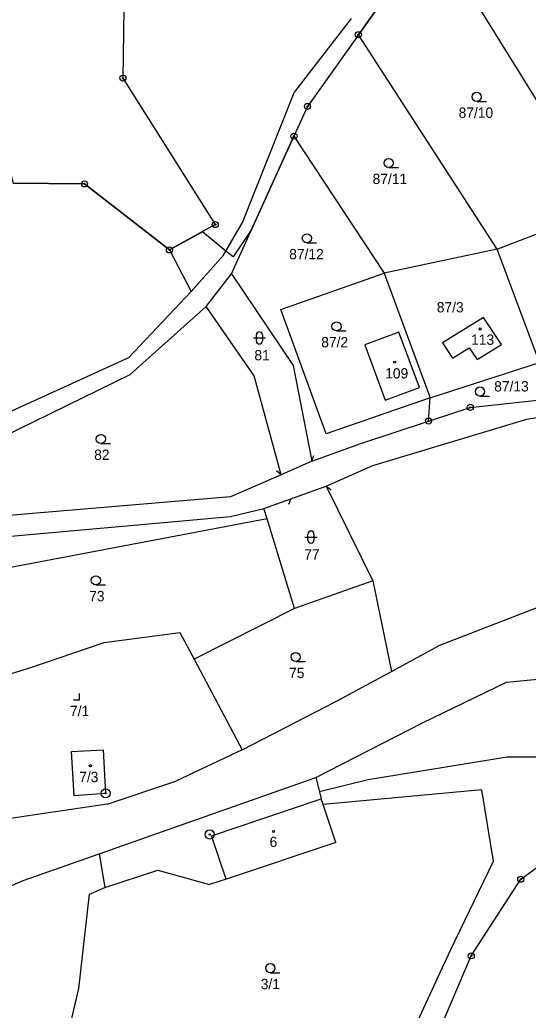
# Model space of a CAD drawing. Extents: x -547623 to -538651, y -1096714 to -1086522.
# Drawn here: x -544678.6 to -544594.9, y -1094562.5 to -1094399.5 of the extents above; entities that cross this region are included whole.
import ezdxf

# ---------------------------------------------------------------- set-up
doc = ezdxf.new("R2010")
doc.units = 0
for name, color, linetype in [('Vrstva 1', 7, 'Continuous'), ('Vrstva 25', 7, 'Continuous'), ('Vrstva 33', 7, 'Continuous'), ('Vrstva 40', 7, 'Continuous'), ('Vrstva 41', 7, 'Continuous'), ('Vrstva 52', 7, 'Continuous'), ('Vrstva 83', 7, 'Continuous'), ('Vrstva 86', 7, 'Continuous'), ('Vrstva 90', 7, 'Continuous'), ('Vrstva 92', 7, 'Continuous')]:
    doc.layers.add(name, color=color, linetype=linetype)

msp = doc.modelspace()

# ---------------------------------------------------------------- linework, layer by layer
at = {"layer": 'Vrstva 1'}
for points in [[(-544622.89, -1094401.93), (-544610.79, -1094384.91)], [(-544610.79, -1094384.91), (-544582.52, -1094430.48)], [(-544624.08, -1094399.23), (-544633.42, -1094411.33)], [(-544622.89, -1094401.93), (-544631.27, -1094413.72)], [(-544600.01, -1094437.2), (-544622.89, -1094401.93)], [(-544641.95, -1094432.83), (-544633.42, -1094411.33)], [(-544631.27, -1094413.72), (-544633.49, -1094418.62)], [(-544643.78, -1094441.26), (-544633.49, -1094418.62)], [(-544633.49, -1094418.62), (-544618.63, -1094441.16)], [(-544600.01, -1094437.2), (-544582.52, -1094430.48)], [(-544645.1, -1094438.2), (-544641.95, -1094432.83)], [(-544654, -1094437.34), (-544650.42, -1094444.2)], [(-544600.01, -1094437.2), (-544618.63, -1094441.16)], [(-544593.06, -1094455.85), (-544600.01, -1094437.2)], [(-544650.42, -1094444.2), (-544645.1, -1094438.2)], [(-544635.64, -1094447.17), (-544618.63, -1094441.16)], [(-544618.63, -1094441.16), (-544611.09, -1094461.67)], [(-544647.95, -1094446.63), (-544643.78, -1094441.26)], [(-544643.78, -1094441.26), (-544633.6, -1094456.35)], [(-544660.7, -1094455.03), (-544650.42, -1094444.2)], [(-544660.47, -1094457.87), (-544647.95, -1094446.63)], [(-544640.06, -1094458.09), (-544647.95, -1094446.63)], [(-544628.17, -1094467.63), (-544635.64, -1094447.17)], [(-544602.27, -1094448.47), (-544609.06, -1094452.61)], [(-544599.29, -1094452.91), (-544602.27, -1094448.47)], [(-544616.21, -1094450.89), (-544621.82, -1094452.97)], [(-544612.84, -1094460), (-544616.21, -1094450.89)], [(-544609.06, -1094452.61), (-544607.38, -1094455.15)], [(-544621.82, -1094452.97), (-544618.48, -1094462.05)], [(-544607.38, -1094455.15), (-544604.64, -1094453.45)], [(-544604.64, -1094453.45), (-544603.3, -1094455.4)], [(-544603.3, -1094455.4), (-544599.29, -1094452.91)], [(-544686.29, -1094466.69), (-544660.7, -1094455.03)], [(-544611.09, -1094461.67), (-544593.06, -1094455.85)], [(-544633.6, -1094456.35), (-544630.56, -1094472.1)], [(-544705.17, -1094479.66), (-544660.47, -1094457.87)], [(-544635.61, -1094474.35), (-544640.06, -1094458.09)], [(-544618.48, -1094462.05), (-544612.84, -1094460)], [(-544611.09, -1094461.67), (-544628.17, -1094467.63)], [(-544611.34, -1094465.51), (-544611.09, -1094461.67)], [(-544604.47, -1094463.25), (-544590.39, -1094461.72)], [(-544611.34, -1094465.51), (-544604.47, -1094463.25)], [(-544595.15, -1094465.22), (-544586.29, -1094463.78)], [(-544622.5, -1094469.18), (-544611.34, -1094465.51)], [(-544620.52, -1094472.8), (-544595.15, -1094465.22)], [(-544630.56, -1094472.1), (-544622.5, -1094469.18)], [(-544630.56, -1094472.1), (-544635.61, -1094474.35)], [(-544628.2, -1094476.24), (-544620.52, -1094472.8)], [(-544635.61, -1094474.35), (-544643.93, -1094478)], [(-544634.01, -1094478.3), (-544628.2, -1094476.24)], [(-544628.2, -1094476.24), (-544620.49, -1094491.8)], [(-544643.93, -1094478), (-544695.48, -1094482.29)], [(-544638.46, -1094479.88), (-544634.01, -1094478.3)], [(-544643.93, -1094481.2), (-544638.46, -1094479.88)], [(-544637.93, -1094481.62), (-544638.46, -1094479.88)], [(-544693.6, -1094485.63), (-544643.93, -1094481.2)], [(-544637.93, -1094481.62), (-544692.61, -1094491.98)], [(-544633.39, -1094496.36), (-544637.93, -1094481.62)], [(-544620.49, -1094491.8), (-544633.39, -1094496.36)], [(-544620.49, -1094491.8), (-544617.45, -1094506.72)], [(-544609.47, -1094502.39), (-544588.64, -1094494.3)], [(-544633.39, -1094496.36), (-544649.95, -1094504.68)], [(-544664.76, -1094501.96), (-544652.27, -1094500.32)], [(-544652.27, -1094500.32), (-544649.95, -1094504.68)], [(-544677.13, -1094506.19), (-544664.76, -1094501.96)], [(-544617.45, -1094506.72), (-544609.47, -1094502.39)], [(-544649.95, -1094504.68), (-544642.01, -1094519.59)], [(-544682.04, -1094507.65), (-544677.13, -1094506.19)], [(-544626.49, -1094511.62), (-544617.45, -1094506.72)], [(-544598.49, -1094508.48), (-544578.51, -1094506.58)], [(-544612.35, -1094515.15), (-544598.49, -1094508.48)], [(-544642.01, -1094519.59), (-544626.49, -1094511.62)], [(-544629.87, -1094524.18), (-544612.35, -1094515.15)], [(-544670.13, -1094519.91), (-544664.93, -1094519.61)], [(-544669.71, -1094527.18), (-544670.13, -1094519.91)], [(-544664.93, -1094519.61), (-544664.52, -1094526.81)], [(-544642.01, -1094519.59), (-544652.94, -1094524.78)], [(-544598.37, -1094520.83), (-544621.29, -1094524.57)], [(-544580.7, -1094520.84), (-544598.37, -1094520.83)], [(-544665.59, -1094536.73), (-544629.87, -1094524.18)], [(-544629.87, -1094524.18), (-544629.3, -1094526.55)], [(-544664.25, -1094528.58), (-544652.94, -1094524.78)], [(-544621.29, -1094524.57), (-544629.3, -1094526.55)], [(-544664.52, -1094526.81), (-544669.71, -1094527.18)], [(-544629.3, -1094526.55), (-544629.02, -1094527.69)], [(-544602.55, -1094526.18), (-544628.7, -1094528.63)], [(-544600.65, -1094537.96), (-544602.55, -1094526.18)], [(-544664.25, -1094528.58), (-544682.08, -1094531.21)], [(-544628.7, -1094528.63), (-544629.02, -1094527.69)], [(-544626.62, -1094534.84), (-544628.7, -1094528.63)], [(-544596.14, -1094540.91), (-544586.8, -1094534.1)], [(-544626.62, -1094534.84), (-544644.68, -1094540.9)], [(-544678.07, -1094541.11), (-544665.59, -1094536.73)], [(-544665.59, -1094536.73), (-544664.64, -1094542.29)], [(-544607.73, -1094552.57), (-544600.65, -1094537.96)], [(-544664.64, -1094542.29), (-544655.9, -1094539.42)], [(-544655.9, -1094539.42), (-544647.38, -1094541.8)], [(-544715.7, -1094557.57), (-544678.07, -1094541.11)], [(-544644.68, -1094540.9), (-544647.38, -1094541.8)], [(-544604.3, -1094553.52), (-544596.14, -1094540.91)], [(-544668.91, -1094558.89), (-544667.17, -1094543.38)], [(-544667.17, -1094543.38), (-544664.64, -1094542.29)], [(-544623.57, -1094598.79), (-544604.3, -1094553.52)], [(-544622.59, -1094584.75), (-544607.73, -1094552.57)], [(-544672.7, -1094575.08), (-544668.91, -1094558.89)]]:
    msp.add_lwpolyline(points, dxfattribs=at)
at = {"layer": 'Vrstva 25'}
for p, q in [((-544603.4, -1094412.9), (-544601.8, -1094412.9)), ((-544617.9, -1094423.8), (-544616.3, -1094423.8)), ((-544631.37, -1094436.18), (-544629.77, -1094436.18)), ((-544626.49, -1094450.67), (-544624.89, -1094450.67)), ((-544640.18, -1094451.81), (-544638.18, -1094451.81)), ((-544639.68, -1094452.31), (-544639.68, -1094451.31)), ((-544638.68, -1094451.31), (-544638.68, -1094452.31)), ((-544602.87, -1094461.39), (-544601.27, -1094461.39)), ((-544665.3, -1094469.2), (-544663.7, -1094469.2)), ((-544631.7, -1094484.6), (-544629.7, -1094484.6)), ((-544631.2, -1094485.1), (-544631.2, -1094484.1)), ((-544630.2, -1094484.1), (-544630.2, -1094485.1)), ((-544666.12, -1094492.46), (-544664.52, -1094492.46)), ((-544633.2, -1094505.1), (-544631.6, -1094505.1)), ((-544637.4, -1094556.3), (-544635.8, -1094556.3))]:
    msp.add_line(p, q, dxfattribs=at)
msp.add_lwpolyline([(-544669.82, -1094511.36), (-544668.82, -1094511.36), (-544668.82, -1094510.36)], dxfattribs=at)
for centre, radius in [((-544603.4, -1094412.15), 0.75), ((-544617.9, -1094423.05), 0.75), ((-544631.37, -1094435.43), 0.75), ((-544626.49, -1094449.92), 0.75), ((-544602.84, -1094450.35), 0.175), ((-544616.9, -1094455.8), 0.175), ((-544602.87, -1094460.64), 0.75), ((-544665.3, -1094468.45), 0.75), ((-544666.12, -1094491.71), 0.75), ((-544633.2, -1094504.35), 0.75), ((-544667.02, -1094522.23), 0.175), ((-544636.86, -1094533.06), 0.175), ((-544637.4, -1094555.55), 0.75)]:
    msp.add_circle(centre, radius, dxfattribs=at)
for centre, start, end in [((-544639.18, -1094451.31), 0, 180), ((-544639.18, -1094452.31), 180, 0), ((-544630.7, -1094484.1), 0, 180), ((-544630.7, -1094485.1), 180, 0)]:
    msp.add_arc(centre, 0.5, start, end, dxfattribs=at)
at = {"layer": 'Vrstva 33'}
for points in [[(-544647.08, -1094533.74), (-544629.02, -1094527.69)], [(-544644.68, -1094540.9), (-544647.08, -1094533.74)]]:
    msp.add_lwpolyline(points, dxfattribs=at)
at = {"layer": 'Vrstva 40'}
for p, q in [((-544630.56, -1094472.1), (-544630.22, -1094471.16)), ((-544635.61, -1094474.35), (-544636.37, -1094473.7)), ((-544628.2, -1094476.24), (-544627.39, -1094476.82)), ((-544634.01, -1094478.3), (-544634.41, -1094479.22))]:
    msp.add_line(p, q, dxfattribs=at)
at = {"layer": 'Vrstva 41'}
for points in [[(-544660.78, -1094347.87), (-544661.66, -1094409.07)], [(-544660.78, -1094347.87), (-544661.66, -1094409.07)], [(-544661.66, -1094409.07), (-544646.45, -1094433.17)], [(-544661.66, -1094409.07), (-544646.45, -1094433.17)], [(-544667.99, -1094426.47), (-544679.72, -1094426.34)], [(-544667.99, -1094426.47), (-544679.72, -1094426.34)], [(-544654, -1094437.34), (-544667.99, -1094426.47)], [(-544654, -1094437.34), (-544667.99, -1094426.47)], [(-544646.45, -1094433.17), (-544654, -1094437.34)], [(-544646.45, -1094433.17), (-544654, -1094437.34)]]:
    msp.add_lwpolyline(points, dxfattribs=at)
at = {"layer": 'Vrstva 52'}
for points in [[(-544714.47, -1094324.84), (-544713.72, -1094325.69), (-544704.05, -1094336.69), (-544690.14, -1094360.29), (-544691.72, -1094381.65), (-544690.48, -1094386.27), (-544679.72, -1094426.34), (-544667.99, -1094426.47), (-544654, -1094437.34), (-544648.57, -1094434.34)], [(-544610.79, -1094384.91), (-544622.89, -1094401.93), (-544631.27, -1094413.72), (-544633.49, -1094418.62), (-544640.47, -1094433.97), (-544643.5, -1094438.5), (-544644.7, -1094437.52), (-544648.57, -1094434.34)]]:
    msp.add_lwpolyline(points, dxfattribs=at)
at = {"layer": 'Vrstva 83'}
for centre, radius in [((-544622.89, -1094401.93), 0.5), ((-544622.89, -1094401.93), 0.1), ((-544661.66, -1094409.07), 0.5), ((-544661.66, -1094409.07), 0.1), ((-544631.27, -1094413.72), 0.5), ((-544631.27, -1094413.72), 0.1), ((-544633.49, -1094418.62), 0.5), ((-544633.49, -1094418.62), 0.1), ((-544667.99, -1094426.47), 0.5), ((-544667.99, -1094426.47), 0.1), ((-544646.45, -1094433.17), 0.5), ((-544646.45, -1094433.17), 0.1), ((-544654, -1094437.34), 0.5), ((-544654, -1094437.34), 0.1), ((-544604.47, -1094463.25), 0.5), ((-544604.47, -1094463.25), 0.1), ((-544611.34, -1094465.51), 0.5), ((-544611.34, -1094465.51), 0.1), ((-544664.52, -1094526.76), 0.75), ((-544664.52, -1094526.76), 0.1), ((-544647.37, -1094533.54), 0.75), ((-544647.37, -1094533.54), 0.1), ((-544596.14, -1094540.91), 0.5), ((-544596.14, -1094540.91), 0.1), ((-544604.3, -1094553.52), 0.5), ((-544604.3, -1094553.52), 0.1)]:
    msp.add_circle(centre, radius, dxfattribs=at)
at = {"layer": 'Vrstva 90'}
for points in [[(-544602.27, -1094448.47), (-544609.06, -1094452.61)], [(-544599.29, -1094452.91), (-544602.27, -1094448.47)], [(-544616.21, -1094450.89), (-544621.82, -1094452.97)], [(-544612.84, -1094460), (-544616.21, -1094450.89)], [(-544609.06, -1094452.61), (-544607.38, -1094455.15)], [(-544621.82, -1094452.97), (-544618.48, -1094462.05)], [(-544607.38, -1094455.15), (-544604.64, -1094453.45)], [(-544604.64, -1094453.45), (-544603.3, -1094455.4)], [(-544603.3, -1094455.4), (-544599.29, -1094452.91)], [(-544618.48, -1094462.05), (-544612.84, -1094460)], [(-544670.13, -1094519.91), (-544664.93, -1094519.61)], [(-544669.71, -1094527.18), (-544670.13, -1094519.91)], [(-544664.93, -1094519.61), (-544664.52, -1094526.81)], [(-544664.52, -1094526.81), (-544669.71, -1094527.18)], [(-544647.08, -1094533.74), (-544629.02, -1094527.69)], [(-544628.7, -1094528.63), (-544629.02, -1094527.69)], [(-544626.62, -1094534.84), (-544628.7, -1094528.63)], [(-544644.68, -1094540.9), (-544647.08, -1094533.74)], [(-544626.62, -1094534.84), (-544644.68, -1094540.9)]]:
    msp.add_lwpolyline(points, dxfattribs=at)

# ---------------------------------------------------------------- texts
at = {"layer": 'Vrstva 86'}
for s, p in [('87/10', (-544606.38, -1094415.6)), ('87/11', (-544620.54, -1094426.5)), ('87/12', (-544634.28, -1094438.88)), ('87/3', (-544609.97, -1094447.62)), ('87/2', (-544629, -1094453.37)), ('81', (-544640.01, -1094455.51)), ('87/13', (-544600.52, -1094460.64)), ('82', (-544666.4, -1094471.9)), ('77', (-544631.8, -1094488.3)), ('73', (-544667.22, -1094495.16)), ('75', (-544634.3, -1094507.8)), ('3/1', (-544638.96, -1094559))]:
    msp.add_text(s, height=1.7, dxfattribs=at).set_placement(p)
at = {"layer": 'Vrstva 92'}
for s, p in [('113', (-544604.32, -1094452.96)), ('109', (-544618.47, -1094458.5)), ('7/1', (-544670.38, -1094514.06)), ('7/3', (-544668.86, -1094524.93)), ('6', (-544637.51, -1094535.61))]:
    msp.add_text(s, height=1.7, dxfattribs=at).set_placement(p)

doc.saveas('drawing.dxf')
